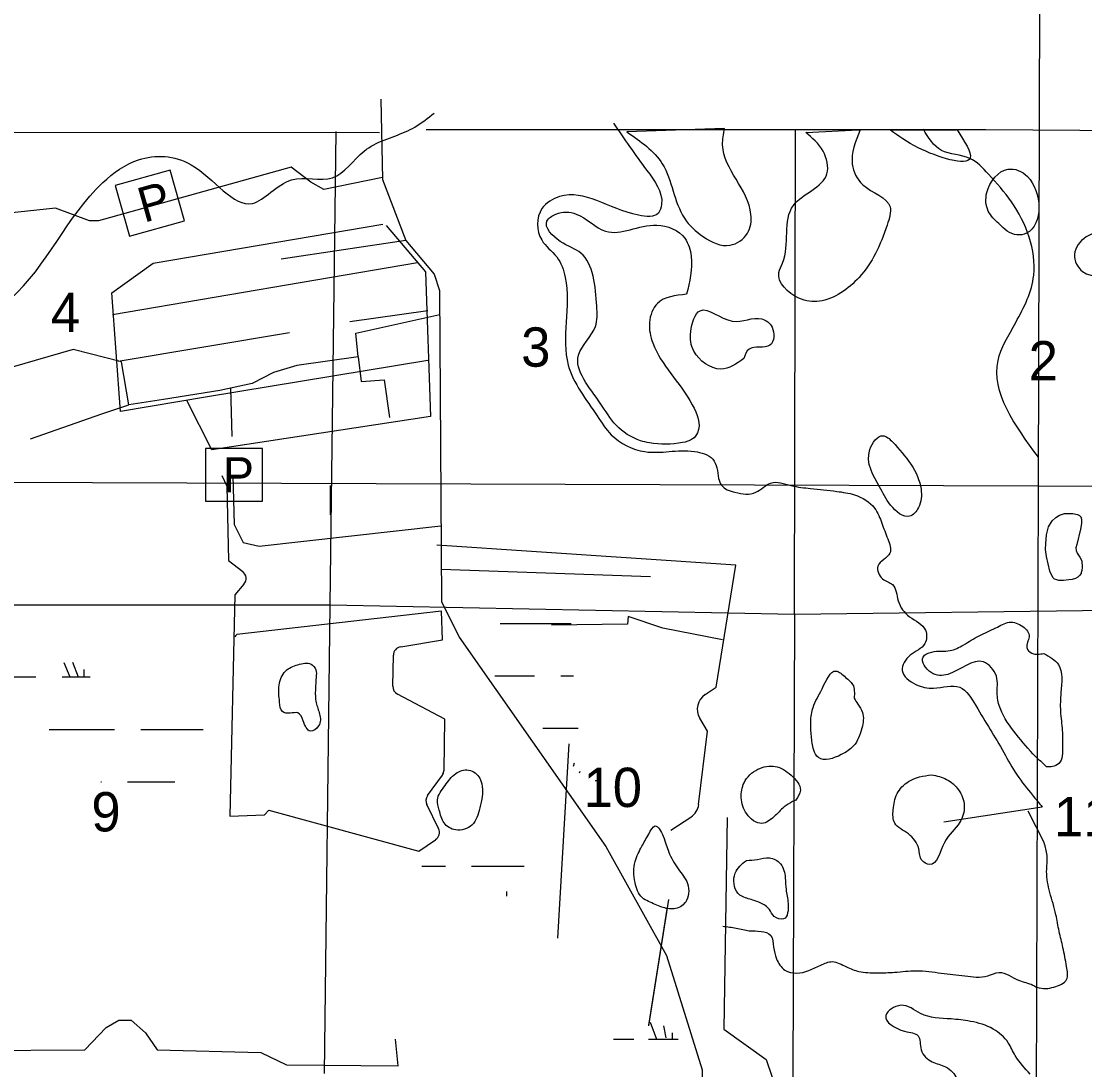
# Model space of a CAD drawing. Extents: x 408847 to 817539, y 923858 to 1151780.
# Drawn here: x 522887 to 535062, y 1099109 to 1111107 of the extents above; entities that cross this region are included whole.
import ezdxf

# ---------------------------------------------------------------- set-up
doc = ezdxf.new("R2010")
doc.units = 0
for name, color, linetype in [('County Boundary', 7, 'Continuous'), ('County Routes Highway Center Lines', 7, 'Continuous'), ('Lakes and Ponds', 7, 'Continuous'), ('Level 12', 7, 'Continuous'), ('Level 43', 7, 'Continuous'), ('Local Roads Paved', 7, 'Continuous'), ('Local Roads Related Cells', 7, 'Continuous'), ('Local Roads Related Text', 7, 'Continuous'), ('Narrow River Creek and Branch and Slough', 7, 'Continuous'), ('Quad Borders', 7, 'Continuous'), ('Section Lines', 7, 'Continuous'), ('Swamps', 7, 'Continuous')]:
    doc.layers.add(name, color=color, linetype=linetype)

msp = doc.modelspace()

# ---------------------------------------------------------------- linework, layer by layer
at = {"layer": 'County Boundary'}
msp.add_lwpolyline([(527521, 1109868), (533930, 1109868), (540932, 1109817), (546230, 1109773), (553555, 1109714), (560417, 1109663), (567777, 1109604), (573538, 1109560), (574298, 1109545), (574284, 1106206), (574225, 1102674), (574115, 1095930), (574078, 1089281), (573979, 1079077)], dxfattribs=at)
at = {"layer": 'County Routes Highway Center Lines'}
msp.add_lwpolyline([(526987, 1109832), (522131, 1109834), (521639, 1109839)], dxfattribs=at)
at = {"layer": 'Lakes and Ponds'}
for p, q in [((530938, 1109881), (529821, 1109840)), ((531869, 1109835), (532470, 1109863)), ((532470, 1109863), (532487, 1109864)), ((532487, 1109864), (532490, 1109863)), ((532840, 1109861), (533595, 1109865)), ((532840, 1109861), (532840, 1109861)), ((534626, 1102575), (534626, 1102575))]:
    msp.add_line(p, q, dxfattribs=at)
msp.add_lwpolyline([(534664, 1104814), (534626, 1104983), (534614, 1105063), (534616, 1105131), (534624, 1105229), (534647, 1105322), (534688, 1105391), (534730, 1105428), (534772, 1105455), (534831, 1105475), (534865, 1105475), (534927, 1105474), (534979, 1105462), (535002, 1105451), (535016, 1105436), (535026, 1105410), (535024, 1105359), (535012, 1105296), (534972, 1105120), (534960, 1105080), (534964, 1105049), (534976, 1105021), (535006, 1104975), (535027, 1104932), (535034, 1104859), (535028, 1104822), (535022, 1104798), (535020, 1104788), (535002, 1104763), (534984, 1104747), (534957, 1104729), (534918, 1104717), (534880, 1104714), (534819, 1104706), (534767, 1104708), (534743, 1104713), (534716, 1104722), (534696, 1104743), (534664, 1104814)], dxfattribs=at)
for points in [[(535955, 1109879), (535903, 1109669), (535688, 1109545), (535636, 1109225), (535417, 1109078), (535275, 1108754), (535050, 1108619), (534944, 1108411), (534982, 1108303), (535095, 1108211), (535412, 1108279), (535895, 1108788), (535895, 1108900), (535711, 1109108), (535908, 1109237), (535926, 1109549), (536261, 1109727), (536575, 1109804), (536529, 1109956)], [(529821, 1109840), (530226, 1109476), (530479, 1108853), (530695, 1108642), (531002, 1108544), (531200, 1108681), (531241, 1108897), (530916, 1109691), (530938, 1109881)], [(532490, 1109863), (532401, 1109471), (532521, 1109237), (532833, 1108983), (532800, 1108775), (532478, 1108176), (532024, 1107904), (531790, 1107938), (531560, 1108233), (531602, 1108339), (531727, 1109000), (532111, 1109361), (532066, 1109620), (531869, 1109835)], [(533601, 1109863), (533750, 1109543), (533156, 1109659), (532840, 1109861)], [(534077, 1108791), (534286, 1108662), (534395, 1108682), (534405, 1109331), (534186, 1109414), (533941, 1109147), (533958, 1108935), (534077, 1108791)], [(530504, 1107983), (530556, 1108418), (530484, 1108623), (530163, 1108774), (529577, 1108704), (529239, 1108901), (529008, 1108900), (528905, 1108820), (529057, 1108587), (529294, 1108453), (529476, 1107846), (529460, 1107614), (529266, 1107286), (529516, 1106737), (529698, 1106485), (529976, 1106307), (530079, 1106282), (530459, 1106286), (530573, 1106327), (530629, 1106397), (530569, 1106719), (530117, 1107426), (530079, 1107661), (530170, 1107878), (530504, 1107983)], [(531159, 1107246), (531219, 1107355), (531458, 1107400), (531482, 1107608), (531366, 1107701), (531026, 1107676), (530658, 1107795), (530551, 1107555), (530587, 1107332), (530896, 1107127), (531159, 1107246)], [(532863, 1106294), (532752, 1106364), (532602, 1106206), (532713, 1105780), (532840, 1105571), (533057, 1105442), (533158, 1105541), (533188, 1105751), (532863, 1106294)], [(534626, 1102575), (534498, 1102695), (534276, 1102949), (534096, 1103239), (534060, 1103401), (534050, 1103613), (533902, 1103775), (533496, 1103633), (533305, 1103653), (533211, 1103831), (533311, 1103889), (533520, 1103905), (533672, 1103969), (533854, 1104075), (534044, 1104165), (534198, 1104229), (534352, 1104181), (534426, 1104063), (534398, 1103939), (534458, 1103875), (534592, 1103873)], [(534592, 1103873), (534760, 1103746), (534789, 1103424), (534784, 1103212), (534805, 1102990), (534809, 1102807), (534764, 1102613), (534694, 1102577), (534626, 1102575)], [(526263, 1103601), (526259, 1103685), (526205, 1103749), (526055, 1103743), (525913, 1103671), (525839, 1103509), (525845, 1103315), (525877, 1103207), (525965, 1103189), (526055, 1103191), (526115, 1103101), (526197, 1102983), (526291, 1103043), (526303, 1103179), (526263, 1103309), (526255, 1103467), (526263, 1103601)], [(532423, 1103359), (532405, 1103518), (532325, 1103599), (532215, 1103671), (532055, 1103469), (531953, 1103255), (531925, 1103091), (531933, 1102927), (531959, 1102767), (532013, 1102681), (532275, 1102715), (532415, 1102815), (532511, 1103019), (532517, 1103197), (532463, 1103293), (532423, 1103359)], [(528167, 1102316), (528137, 1102444), (528009, 1102538), (527861, 1102498), (527739, 1102360), (527651, 1102196), (527673, 1102079), (527727, 1101933), (527861, 1101853), (528045, 1101907), (528137, 1102104), (528165, 1102240), (528167, 1102316)], [(531756, 1102195), (531807, 1102307), (531700, 1102479), (531518, 1102579), (531320, 1102547), (531162, 1102393), (531130, 1102222), (531192, 1102036), (531366, 1101928), (531502, 1102002), (531622, 1102116), (531717, 1102177), (531756, 1102195)], [(533309, 1102485), (533043, 1102407), (532915, 1102268), (532869, 1102084), (532887, 1101930), (533043, 1101808), (533161, 1101636), (533201, 1101502), (533283, 1101458), (533457, 1101710), (533631, 1101940), (533683, 1102128), (533617, 1102311), (533481, 1102431), (533309, 1102485)], [(530068, 1101034), (530220, 1100970), (530360, 1100950), (530490, 1101024), (530514, 1101238), (530408, 1101406), (530300, 1101600), (530236, 1101780), (530144, 1101898), (530070, 1101806), (529992, 1101666), (529916, 1101492), (529914, 1101250), (529996, 1101078), (530068, 1101034)], [(531188, 1101504), (531060, 1101358), (531048, 1101236), (531090, 1101130), (531210, 1101066), (531346, 1101020), (531452, 1100942), (531508, 1100864), (531614, 1100834), (531666, 1101010), (531642, 1101172), (531634, 1101306), (531580, 1101464), (531452, 1101534), (531314, 1101516), (531188, 1101504)], [(534439, 1099058), (534267, 1099270), (534185, 1099418), (534015, 1099574), (533753, 1099662), (533531, 1099690), (533181, 1099752), (532957, 1099846), (532785, 1099728), (532999, 1099550), (533155, 1099496), (533190, 1099338), (533317, 1099198), (533469, 1099142), (533589, 1099008), (533465, 1098832), (533381, 1098678), (533537, 1098606), (533779, 1098578), (534063, 1098414), (534189, 1098254), (534235, 1098072), (534349, 1097980), (534463, 1097976), (534540, 1098010)]]:
    msp.add_spline(points, degree=3, dxfattribs=at)
at = {"layer": 'Level 12'}
for p, q in [((527425, 1108344), (523930, 1107748)), ((527542, 1107795), (526649, 1107667)), ((525958, 1107543), (523996, 1107212)), ((525339, 1104073), (525331, 1104061)), ((525357, 1104091), (525339, 1104073)), ((529154, 1102839), (529028, 1100616)), ((534597, 1101708), (534415, 1102068)), ((530296, 1101058), (530066, 1099612))]:
    msp.add_line(p, q, dxfattribs=at)
msp.add_arc((527628, 1102539), 100, 324.184, 359.0247, dxfattribs=at)
for points in [[(534514, 1100052), (534617, 1100038), (534707, 1100054), (534855, 1100141), (534854, 1100289), (534813, 1100507), (534769, 1100693), (534732, 1100883), (534663, 1101137), (534626, 1101378), (534630, 1101562), (534597, 1101708)], [(530918, 1100750), (531070, 1100730), (531222, 1100700), (531356, 1100692), (531468, 1100646), (531500, 1100512), (531534, 1100378), (531630, 1100248), (531762, 1100214), (532041, 1100306), (532171, 1100346), (532333, 1100286), (532477, 1100234), (532681, 1100218), (532885, 1100224), (533135, 1100242), (533419, 1100214), (533689, 1100182), (533951, 1100184), (534081, 1100222), (534305, 1100132), (534467, 1100078), (534515, 1100052)]]:
    msp.add_spline(points, degree=3, dxfattribs=at)
at = {"layer": 'Local Roads Paved'}
for p, q in [((527289, 1108599), (525862, 1108386)), ((527695, 1104836), (530090, 1104753))]:
    msp.add_line(p, q, dxfattribs=at)
for points in [[(527002, 1110216), (527022, 1109296), (527288, 1108600), (527615, 1108211), (527677, 1108027), (527697, 1104467), (527902, 1104057), (529579, 1101663), (530274, 1100415), (530683, 1099106), (530683, 1098021), (531757, 1096084)], [(527022, 1109318), (526353, 1109181), (526201, 1109265), (525979, 1109439), (524512, 1109031)], [(524512, 1109031), (523771, 1108825), (523668, 1108825), (523280, 1108968), (522134, 1108845), (521900, 1108700), (521068, 1108664)], [(526746, 1107265), (526716, 1107536), (527678, 1107750)], [(524517, 1106780), (524118, 1106718), (524036, 1107209), (523480, 1107350), (521500, 1106779), (521190, 1106761)], [(526746, 1107265), (526041, 1107168), (525775, 1107086), (525529, 1106963), (525161, 1106881), (524517, 1106780)], [(526746, 1107265), (526777, 1106984), (527043, 1107004), (527104, 1106574)], [(525282, 1106908), (525297, 1106356)], [(522993, 1106329), (523811, 1106615), (524118, 1106718)], [(525310, 1105907), (525325, 1105347), (525427, 1105142), (525611, 1105101), (527692, 1105332)], [(519667, 1099347), (520158, 1099327), (520332, 1099490), (520444, 1099542), (520700, 1099450), (520833, 1099337), (521814, 1099327), (521937, 1099450), (522029, 1099490), (522182, 1099460), (522326, 1099368), (522377, 1099327), (523614, 1099337), (523860, 1099593), (524003, 1099675), (524146, 1099675), (524309, 1099531), (524442, 1099337), (525629, 1099306), (525925, 1099163), (527203, 1099153), (527173, 1099460)]]:
    msp.add_lwpolyline(points, dxfattribs=at)
at = {"layer": 'Local Roads Related Cells'}
for p, q in [((524592, 1109404), (523964, 1109227)), ((524756, 1108824), (524592, 1109404)), ((523964, 1109227), (524128, 1108646)), ((524128, 1108646), (524756, 1108824)), ((524996, 1106218), (524996, 1105614)), ((525649, 1106218), (524996, 1106218)), ((525649, 1105614), (525649, 1106218)), ((524996, 1105614), (525649, 1105614))]:
    msp.add_line(p, q, dxfattribs=at)
at = {"layer": 'Narrow River Creek and Branch and Slough'}
for p, q in [((525068, 1106203), (524782, 1106768)), ((525184, 1105907), (525241, 1105785)), ((525241, 1105785), (525259, 1104937)), ((531066, 1104883), (527644, 1105113)), ((525259, 1104937), (525423, 1104810)), ((530844, 1103485), (531066, 1104883)), ((525437, 1104666), (525333, 1104545)), ((525333, 1104545), (525275, 1102012)), ((527698, 1104357), (525357, 1104091)), ((527710, 1104029), (527698, 1104357)), ((529834, 1104297), (529826, 1104207)), ((530232, 1104161), (529834, 1104297)), ((529826, 1104207), (528956, 1104197)), ((530916, 1104027), (530232, 1104161)), ((527231, 1103949), (527710, 1104029)), ((527140, 1103498), (527147, 1103852)), ((527738, 1103119), (527194, 1103408)), ((530717, 1103401), (530844, 1103485)), ((530742, 1102983), (530654, 1103132)), ((527728, 1102537), (527738, 1103119)), ((530642, 1102145), (530742, 1102983)), ((527709, 1102481), (527728, 1102537)), ((527539, 1102245), (527709, 1102481)), ((525671, 1102026), (525723, 1102078)), ((525723, 1102078), (527440, 1101610)), ((527664, 1101868), (527530, 1102142)), ((534576, 1102115), (533449, 1101942)), ((525275, 1102012), (525671, 1102026)), ((530324, 1101852), (530552, 1102000)), ((530968, 1101994), (530930, 1099572)), ((527440, 1101610), (527631, 1101741)), ((530930, 1099572), (531414, 1099226)), ((531414, 1099226), (531696, 1098416))]:
    msp.add_line(p, q, dxfattribs=at)
for points in [[(525019, 1106808), (524025, 1106643), (523926, 1108000), (524399, 1108338), (527027, 1108784)], [(527063, 1108769), (527516, 1108240), (527571, 1106585), (525068, 1106203)], [(527540, 1107226), (525019, 1106808)], [(530279, 1100948), (530067, 1099617)]]:
    msp.add_lwpolyline(points, dxfattribs=at)
for centre, radius, start, end in [((525361, 1104731), 100, 319.3045, 52.1248), ((527247, 1103850), 100, 99.5021, 178.8841), ((527240, 1103496), 100, 178.884, 242.0358), ((530826, 1103234), 200, 123.3406, 210.5404), ((527620, 1102186), 100, 144.1839, 206.0034), ((530444, 1102168), 200, 302.9695, 353.1872), ((527574, 1101824), 100, 304.4792, 26.0033)]:
    msp.add_arc(centre, radius, start, end, dxfattribs=at)
for points in [[(520208, 1109811), (520447, 1109095), (520380, 1108865), (520762, 1108163), (521096, 1107928), (521543, 1107913), (522081, 1107670), (522443, 1107723), (522765, 1107932), (523821, 1109260), (524231, 1109522), (524833, 1109464), (525534, 1109023), (525980, 1109291), (526449, 1109315), (526813, 1109622), (527284, 1109842), (527391, 1109896), (527615, 1110057)], [(529668, 1109940), (530049, 1109400), (530218, 1109013), (530181, 1108912), (529954, 1108887), (529050, 1109100), (528848, 1108963), (528845, 1108604), (529017, 1108411), (529115, 1108176), (529149, 1107172), (529481, 1106590), (529641, 1106376), (530026, 1106182), (530593, 1106184), (530803, 1106095), (530870, 1105875)], [(534531, 1106117), (534069, 1107223), (534272, 1107660), (534478, 1108200), (534222, 1109041), (533959, 1109357), (533748, 1109537), (533421, 1109629), (533215, 1109871)], [(530870, 1105875), (530904, 1105797), (531058, 1105717), (531296, 1105717), (531466, 1105823), (531702, 1105793), (531923, 1105761), (532223, 1105727), (532427, 1105687), (532657, 1105535), (532739, 1105363), (532807, 1105183), (532831, 1105019), (532695, 1104871), (532747, 1104727), (532861, 1104661), (532927, 1104475), (533057, 1104293), (533239, 1104137), (533231, 1103985), (533063, 1103851), (532973, 1103679), (533129, 1103517), (533331, 1103475), (533631, 1103485), (533815, 1103275), (533979, 1103003), (534135, 1102739), (534287, 1102481), (534463, 1102252), (534576, 1102115)]]:
    msp.add_spline(points, degree=3, dxfattribs=at)
at = {"layer": 'Quad Borders'}
for p, q in [((534664, 1151230), (534527, 1105790)), ((493959, 1105933), (534527, 1105790)), ((534527, 1105790), (534390, 1060351)), ((534527, 1105790), (575095, 1105688))]:
    msp.add_line(p, q, dxfattribs=at)
at = {"layer": 'Section Lines'}
for p, q in [((526423, 1104430), (526493, 1109847)), ((531739, 1104322), (531749, 1109857)), ((526426, 1105460), (526429, 1105795)), ((521062, 1104426), (526423, 1104430)), ((526360, 1099065), (526423, 1104430)), ((526423, 1104430), (531739, 1104322)), ((531739, 1104322), (536982, 1104391)), ((531739, 1104322), (531719, 1099027))]:
    msp.add_line(p, q, dxfattribs=at)
at = {"layer": 'Swamps'}
for p, q in [((523374, 1103769), (523445, 1103603)), ((522605, 1103603), (523055, 1103603)), ((523205, 1103003), (523955, 1103003)), ((524255, 1103003), (524705, 1103003)), ((528043, 1101439), (528643, 1101439)), ((530086, 1099653), (530158, 1099459))]:
    msp.add_line(p, q, dxfattribs=at)
for points in [[(528369, 1104217), (529181, 1104217)], [(523472, 1103771), (523538, 1103603)], [(523604, 1103690), (523604, 1103603)], [(528309, 1103617), (528763, 1103617)], [(529063, 1103617), (529210, 1103617)], [(523355, 1103603), (523677, 1103603)], [(528859, 1103017), (529263, 1103017)], [(524705, 1103003), (524971, 1103003)], [(529208, 1102581), (529220, 1102621)], [(529279, 1102507), (529287, 1102525)], [(523798, 1102403), (523805, 1102403)], [(524105, 1102403), (524646, 1102403)], [(529458, 1102417), (529488, 1102417)], [(527473, 1101439), (527743, 1101439)], [(528442, 1101150), (528442, 1101093)], [(530240, 1099611), (530267, 1099472)], [(530339, 1099531), (530339, 1099459)], [(529667, 1099459), (529899, 1099459)], [(530068, 1099459), (530409, 1099459)]]:
    msp.add_lwpolyline(points, dxfattribs=at)

# ---------------------------------------------------------------- texts
at = {"layer": 'Level 43'}
for s, p in [('4', (523226, 1107550)), ('10', (529324, 1102115)), ('9', (523690, 1101836)), ('11', (534711, 1101780))]:
    msp.add_text(s, height=450, rotation=360, dxfattribs=at).set_placement(p)
for s, p in [('3', (528610, 1107154)), ('2', (534420, 1106997))]:
    msp.add_text(s, height=450, dxfattribs=at).set_placement(p)
at = {"layer": 'Local Roads Related Text'}
msp.add_text('P', height=400, rotation=15.7602, dxfattribs=at).set_placement((524291, 1108800))
msp.add_text('P', height=400, dxfattribs=at).set_placement((525195, 1105718))

doc.saveas('drawing.dxf')
